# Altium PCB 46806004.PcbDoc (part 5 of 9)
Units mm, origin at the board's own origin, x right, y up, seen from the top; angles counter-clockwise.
Board outline 130 x 105 mm, 8 copper layers (Top Layer, P1-GND, L1-Signal, L2-Signal, L3-Signal, L4-Signal, P2-GND, Bottom Layer), stack 1.63 mm thick; 796 components, 496 nets, 2808 pads, 1195 vias.
Unrouted connection lines stored in the file: 1.
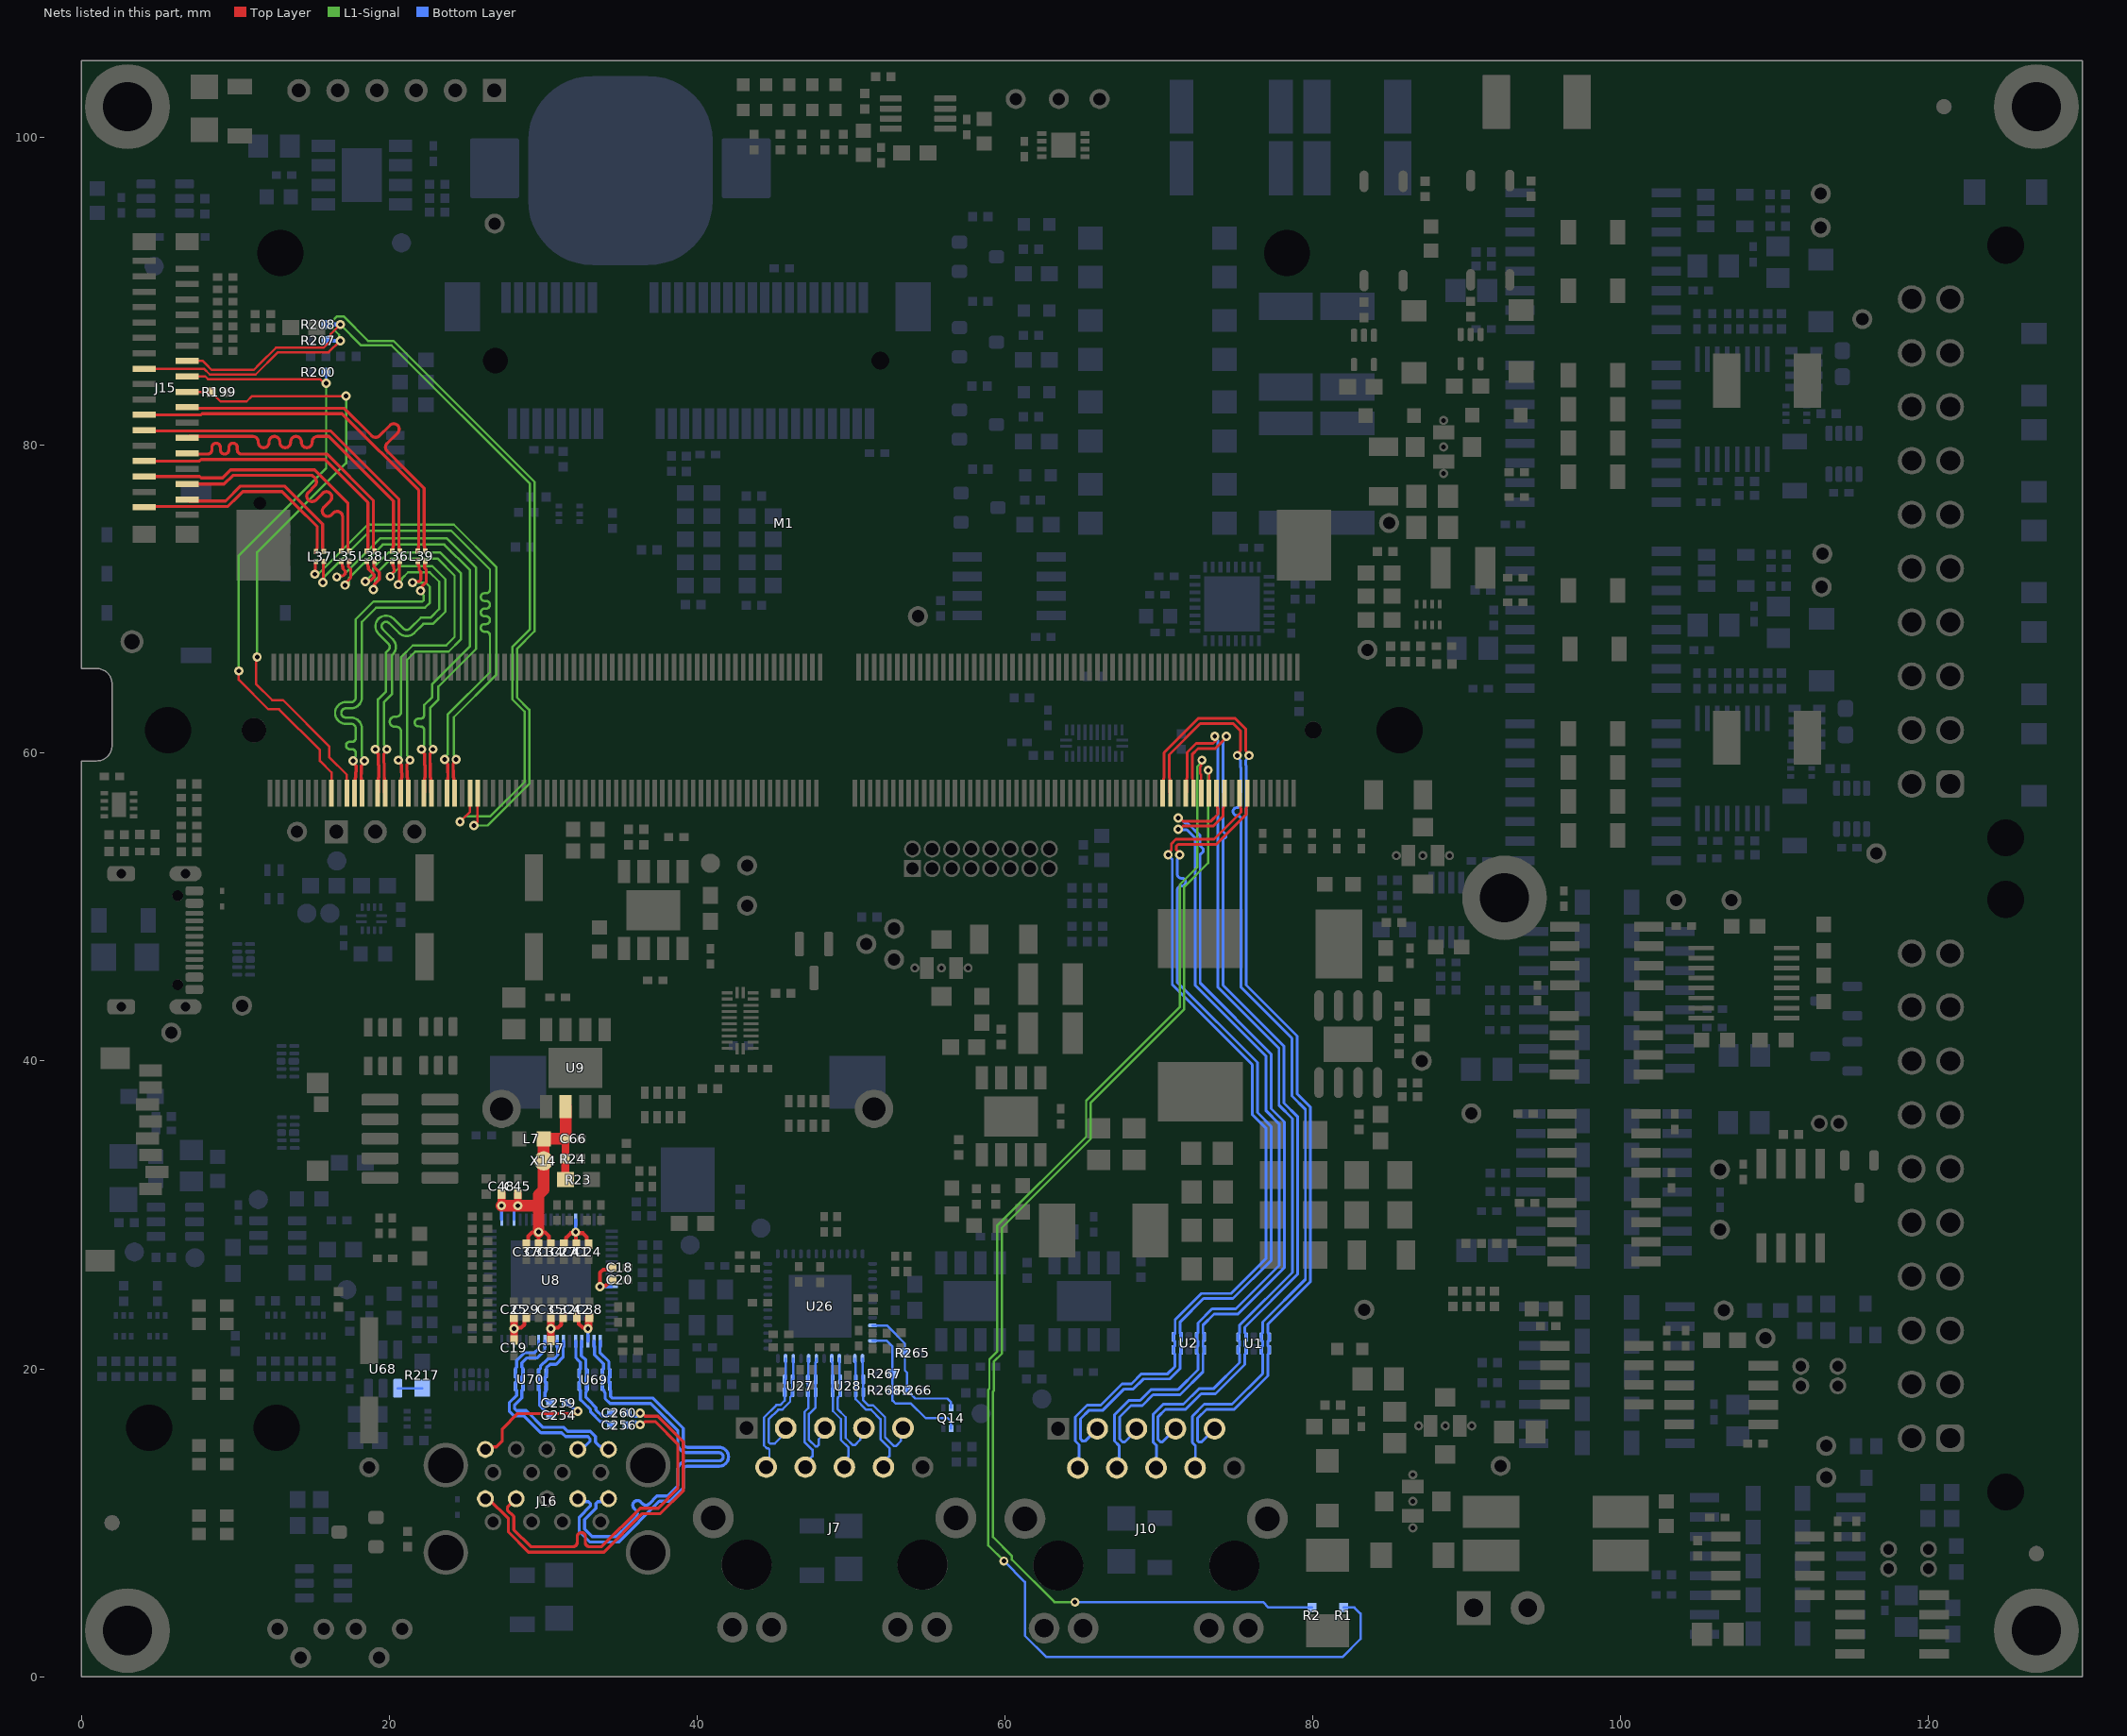
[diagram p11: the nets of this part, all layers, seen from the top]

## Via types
v1: diameter 0.6, hole 0.3, Top Layer to Bottom Layer, tented both sides, 1130 vias
v2: diameter 0.6, hole 0.3, Top Layer to Bottom Layer, 53 vias
v3: diameter 0.3, hole 0.3, Top Layer to Bottom Layer, 12 vias

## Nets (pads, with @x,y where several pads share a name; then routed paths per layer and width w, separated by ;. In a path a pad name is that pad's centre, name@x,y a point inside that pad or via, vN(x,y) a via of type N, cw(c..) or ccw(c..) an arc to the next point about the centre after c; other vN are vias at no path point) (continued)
DS2_P: C259.1 J16.U9 | length 8.5
  Top Layer w0.2: J16.U9@26.25,14.769 26.422,14.941 26.958,14.941 27.35,15.333 27.35,15.644 27.35,16.1 28.35,17.1 30.175,17.1 30.186,17.088 31.982,17.088 32.143,17.249 v1(32.251,17.249)
  Bottom Layer w0.2: C259.1@31.5,17.8 31.55,17.8 31.85,17.5 31.904,17.5 32.154,17.249 v1(32.251,17.249)
DS2_RX_N: J16.U5 U8.44 U70.4 U70.7 | length 13.2
  Bottom Layer w0.2: U8.44@30.111,21.8 30.109,21.798 30.109,21.224 29.592,20.707 28.935,20.707 28.625,20.396 28.625,20.117 28.675,20.067 28.675,19.742 U70.7@28.7,19.717 28.7,19.529 28.675,19.504 28.634,19.504 28.625,19.496 28.625,19.146 28.7,19.071 U70.4@28.7,18.883 28.7,18.695 28.625,18.62 28.625,18.13 28.15,17.655 28.15,17.407 28.267,17.29 28.91,17.29 30,16.2 31.35,16.2 31.599,15.951 33.058,15.951 33.4,15.609 33.4,15.25 33.69,14.96 33.788,14.96 33.881,14.867 33.881,14.769 J16.U5@34.25,14.769
DS2_RX_P: J16.U6 U8.45 U70.5 U70.6 | length 13
  Bottom Layer w0.2: U8.45@29.711,21.8 29.709,21.798 29.709,21.319 29.447,21.057 28.79,21.057 28.275,20.541 28.275,20.117 28.225,20.067 28.225,19.742 U70.6@28.2,19.717 28.2,19.529 28.225,19.504 28.266,19.504 28.275,19.496 28.275,19.146 28.2,19.071 U70.5@28.2,18.883 28.2,18.695 28.275,18.62 28.275,18.275 27.8,17.8 27.8,17.262 28.122,16.94 28.765,16.94 29.855,15.85 31.205,15.85 31.454,15.601 32.913,15.601 33.05,15.464 33.05,15.298 32.521,14.769 J16.U6@32.25,14.769
DS2_TX_N: C254.2 U8.42 U70.2 U70.9 | length 6
  Bottom Layer w0.2: C254.2@30.5,17 30.4,17.1 30.35,17.1 30.15,17.3 30.096,17.3 29.775,17.621 29.775,18.621 29.7,18.695 U70.2@29.7,18.883 29.7,19.071 29.775,19.145 29.775,19.496 29.766,19.504 29.725,19.504 29.7,19.529 U70.9@29.7,19.717 29.7,19.904 29.825,20.029 29.825,20.174 30.301,20.65 30.7,20.65 30.948,20.898 30.948,21.396 30.913,21.431 30.913,21.798 U8.42@30.911,21.8
DS2_TX_P: C259.2 U8.41 U70.1 U70.10 | length 5
  Bottom Layer w0.2: C259.2@30.5,17.8 30.35,17.95 30.242,17.95 30.125,18.067 30.125,18.483 30.175,18.533 30.175,18.858 U70.1@30.2,18.883 30.2,19.071 30.125,19.146 30.125,19.454 30.2,19.529 U70.10@30.2,19.717 30.225,19.742 30.225,20.08 30.445,20.3 30.845,20.3 31.298,20.753 31.298,21.408 31.309,21.419 31.309,21.798 U8.41@31.311,21.8
DS3_N: C256.1 J16.L8 | length 23.5
  Top Layer w0.2: J16.L8@28.25,11.569 27.681,11 27.681,10.835 28.1,10.416 28.1,9.545 29.195,8.45 30.665,8.45 31.95,8.45 ccw(c31.95,8.715) 32.215,8.715 32.215,9.102 cw(c32.481,9.102) 32.746,9.102 32.746,8.715 ccw(c33.011,8.715) 33.011,8.45 33.641,8.45 33.805,8.45 36.305,10.95 37.472,10.95 38.75,12.228 38.75,15.125 37.3,16.575 36.608,16.575 36.408,16.375 v1(36.3,16.375)
  Bottom Layer w0.2: C256.1@35.45,16.35 35.5,16.35 35.725,16.575 36.005,16.575 36.074,16.506 36.169,16.506 v1(36.3,16.375)
DS3_P: C260.1 J16.L9 | length 24.3
  Top Layer w0.2: J16.L9@26.25,11.569 26.452,11.569 27.75,10.271 27.75,9.4 29.05,8.1 33.95,8.1 36.45,10.6 37.617,10.6 39.1,12.083 39.1,15.27 37.445,16.925 36.608,16.925 36.408,17.125 v1(36.3,17.125) v1@36.272,17.125
  Bottom Layer w0.2: C260.1@35.45,17.15 35.5,17.15 35.725,16.925 36.1,16.925 v1(36.3,17.125)
DS3_RX_N: J16.L5 U8.36 U69.4 U69.7 | length 30.1
  Bottom Layer w0.2: U8.36@33.311,21.8 33.311,21.498 33.336,21.473 33.336,20.919 33.925,20.33 33.925,19.98 33.85,19.904 U69.4@33.85,19.717 33.85,19.529 33.875,19.504 33.916,19.504 33.925,19.496 33.925,19.104 33.916,19.096 33.875,19.096 33.85,19.071 33.85,18.695 33.975,18.57 33.975,18.504 34.032,18.447 34.032,18.072 34.354,17.75 37,17.75 38.75,16 38.75,15.448 38.75,15.173 ccw(c39.365,15.173) 39.365,14.558 41.432,14.558 cw(c41.432,14.293) 41.697,14.293 cw(c41.432,14.293) 41.432,14.028 39.365,14.028 ccw(c39.365,13.413) 38.75,13.413 38.75,12.446 38.75,12.4 38.1,11.75 37.405,11.75 37.391,11.736 36.892,11.237 cw(c36.677,11.451) 36.463,11.237 36.342,11.358 ccw(c36.127,11.144) 35.913,11.358 ccw(c36.127,11.144) 35.913,10.93 36.034,10.808 cw(c35.82,10.594) 36.034,10.379 35.563,9.908 34.755,9.1 33.195,9.1 32.7,9.595 32.7,10.221 33.425,10.946 33.425,11.257 33.546,11.378 34.059,11.378 J16.L5@34.25,11.569
DS3_RX_P: J16.L6 U8.35 U69.5 U69.6 | length 30.2
  Bottom Layer w0.2: J16.L6@32.25,11.569 32.441,11.378 32.954,11.378 33.075,11.257 33.075,11.091 32.35,10.366 32.35,9.45 33.05,8.75 34.9,8.75 37.55,11.4 38.245,11.4 39.1,12.255 39.1,12.446 39.1,13.413 cw(c39.365,13.413) 39.365,13.678 41.432,13.678 ccw(c41.432,14.293) 42.047,14.293 ccw(c41.432,14.293) 41.432,14.908 39.365,14.908 cw(c39.365,15.173) 39.1,15.173 39.1,15.448 39.1,16.145 37.145,18.1 34.499,18.1 34.382,18.217 34.382,18.592 34.375,18.599 34.375,18.858 U69.6@34.35,18.883 34.35,19.071 34.325,19.096 34.284,19.096 34.275,19.104 34.275,19.496 34.284,19.504 34.325,19.504 34.35,19.529 U69.5@34.35,19.717 34.35,19.904 34.275,19.98 34.275,20.475 33.686,21.064 33.686,21.473 33.711,21.498 U8.35@33.711,21.8
DS3_TX_N: C256.2 U8.39 U69.1 U69.10 | length 6.9
  Bottom Layer w0.2: U8.39@32.111,21.8 32.111,21.498 32.136,21.473 32.136,20.714 32.25,20.6 32.425,20.425 32.425,19.979 32.35,19.904 U69.1@32.35,19.717 32.35,19.529 32.375,19.504 32.416,19.504 32.425,19.496 32.425,19.145 32.35,19.071 U69.10@32.35,18.883 32.35,18.695 32.425,18.621 32.425,18.006 32.619,17.811 33.086,17.344 33.086,17.194 33.705,16.575 34.175,16.575 34.4,16.35 C256.2@34.45,16.35
DS3_TX_P: C260.2 U8.38 U69.2 U69.9 | length 6.3
  Bottom Layer w0.2: U8.38@32.511,21.8 32.511,21.498 32.486,21.473 32.486,20.859 32.775,20.57 32.775,19.98 32.85,19.904 U69.2@32.85,19.717 32.85,19.529 32.775,19.454 32.775,19.146 32.85,19.071 U69.9@32.85,18.883 32.825,18.858 32.825,18.533 32.775,18.483 32.775,18.151 32.969,17.956 33.436,17.489 33.436,17.339 33.85,16.925 34.175,16.925 34.4,17.15 C260.2@34.45,17.15
DSI_1_CLK_CON_N: J15.9 L38.3 | length 18.6
  Top Layer w0.2: J15.9@6.881,79.478 6.931,79.428 8.111,79.428 8.211,79.428 ccw(c8.211,79.703) 8.486,79.703 8.486,79.866 cw(c8.761,79.866) 8.761,80.141 cw(c8.761,79.866) 9.036,79.866 9.036,79.703 ccw(c9.311,79.703) 9.311,79.428 ccw(c9.311,79.703) 9.586,79.703 9.586,79.866 cw(c9.861,79.866) 9.861,80.141 cw(c9.861,79.866) 10.136,79.866 10.136,79.703 ccw(c10.411,79.703) 10.411,79.428 10.931,79.428 15.972,79.428 18.975,76.425 18.975,73.345 19,73.32 19,73.175 L38.3@19.05,73.125
DSI_1_CLK_CON_P: J15.8 L38.4 | length 18.9
  Top Layer w0.2: J15.8@4.081,78.978 7.685,78.978 7.785,79.078 15.827,79.078 18.625,76.28 18.625,73.317 18.6,73.292 18.6,73.175 L38.4@18.55,73.125
DSI_1_CLK_N: L38.2 M1.35 | length 27.2
  Top Layer w0.2: v1(18.98,70.63) 19.056,70.706 19.056,70.989 19.365,71.298 19.365,71.753 19,72.118 19,72.425 L38.2@19.05,72.475 ; v1(20.6,59.55) 20.6,59.442 20.8,59.242 20.8,58.729 20.825,58.704 20.825,58.424 20.8,58.399 20.8,57.45 M1.35@20.75,57.4
  L1-Signal w0.15: v1(18.98,70.63) 19.066,70.716 19.066,71.211 19.35,71.495 19.35,71.859 20.141,72.65 23.134,72.65 24.25,71.534 24.25,67.55 23.7,67 21.534,67 20.775,66.241 20.775,63.419 20.775,62.694 cw(c20.45,62.694) 20.45,62.369 20.365,62.369 ccw(c20.365,62.044) 20.04,62.044 ccw(c20.365,62.044) 20.365,61.719 20.45,61.719 cw(c20.45,61.394) 20.775,61.394 20.775,60.444 20.775,59.847 20.6,59.672 v1(20.6,59.55)
DSI_1_CLK_P: L38.1 M1.37 | length 26.9
  Top Layer w0.2: v1(18.449,71.16) 18.526,71.236 18.809,71.236 19.015,71.443 19.015,71.608 18.65,71.973 18.65,72.126 18.6,72.176 18.6,72.425 L38.1@18.55,72.475 ; M1.37@21.25,57.4 21.2,57.45 21.2,58.399 21.175,58.424 21.175,58.849 21.15,58.874 21.15,59.242 21.35,59.442 v1(21.35,59.55)
  L1-Signal w0.15: v1(18.449,71.16) 18.95,71.661 18.95,72.025 19.975,73.05 23.3,73.05 24.65,71.7 24.65,67.384 23.866,66.6 21.7,66.6 21.175,66.075 21.175,59.847 21.35,59.672 v1(21.35,59.55)
DSI_1_D0_CON_N: J15.3 L37.3 | length 12.1
  Top Layer w0.2: J15.3@6.881,76.478 6.981,76.378 9.378,76.378 10.35,77.35 13.2,77.35 15.675,74.875 15.675,73.32 15.7,73.295 15.7,73.15 L37.3@15.75,73.1
DSI_1_D0_CON_P: J15.2 L37.4 | length 14.3
  Top Layer w0.2: J15.2@4.081,75.978 4.131,76.028 7.733,76.028 9.523,76.028 10.153,76.658 10.495,77 13.055,77 13.939,76.116 15.325,74.73 15.325,74.218 15.325,73.32 15.3,73.295 15.3,73.15 L37.4@15.25,73.1
DSI_1_D0_N: L37.2 M1.47 | length 33
  Top Layer w0.2: v1(15.7,71.1) 15.725,71.125 15.725,72.425 L37.2@15.75,72.45 ; v1(23.6,59.6) 23.6,59.492 23.8,59.292 23.8,58.757 23.825,58.732 23.825,58.424 23.8,58.399 23.8,57.45 M1.47@23.75,57.4
  L1-Signal w0.15: v1(15.7,71.1) 15.779,71.179 15.779,71.463 18.766,74.45 24.034,74.45 26.55,71.934 26.55,71.217 26.55,70.642 cw(c26.3,70.642) 26.3,70.392 26.2,70.392 ccw(c26.2,70.142) 26.2,69.892 26.3,69.892 cw(c26.3,69.642) 26.3,69.392 26.2,69.392 ccw(c26.2,69.142) 26.2,68.892 26.3,68.892 cw(c26.3,68.642) 26.3,68.392 26.2,68.392 ccw(c26.2,68.142) 26.2,67.892 26.3,67.892 cw(c26.3,67.642) 26.55,67.642 26.55,66.426 26.55,65.25 23.8,62.5 23.8,59.922 23.6,59.722 v1(23.6,59.6)
DSI_1_D0_P: L37.1 M1.49 | length 31.1
  Top Layer w0.2: v1(15.17,71.63) 15.21,71.67 15.21,72.41 L37.1@15.25,72.45 ; M1.49@24.25,57.4 24.2,57.45 24.2,58.399 24.175,58.424 24.175,58.876 24.15,58.901 24.15,59.292 24.35,59.492 v1(24.35,59.6)
  L1-Signal w0.15: v1(15.17,71.63) 15.256,71.716 15.466,71.716 18.6,74.85 24.2,74.85 26.95,72.1 26.95,65.084 24.2,62.334 24.2,59.872 24.35,59.722 v1(24.35,59.6)
DSI_1_D1_CON_N: J15.6 L35.3 | length 17.5
  Top Layer w0.2: J15.6@4.081,77.978 7.685,77.978 7.785,77.878 9.178,77.878 9.7,78.4 15.15,78.4 17.325,76.225 17.325,73.345 17.35,73.32 17.35,73.175 L35.3@17.4,73.125
DSI_1_D1_CON_P: J15.5 L35.4 | length 17.5
  Top Layer w0.2: J15.5@6.881,77.478 9.273,77.478 9.845,78.05 14.472,78.05 15.005,78.05 15.181,77.874 cw(c14.933,77.627) 15.181,77.379 14.747,76.946 ccw(c14.994,76.698) 14.747,76.451 ccw(c14.994,76.698) 15.242,76.451 15.676,76.884 cw(c15.923,76.637) 16.171,76.884 cw(c15.923,76.637) 16.171,76.389 15.758,75.977 ccw(c16.006,75.73) 15.758,75.482 ccw(c16.006,75.73) 16.253,75.482 16.378,75.606 cw(c16.625,75.359) 16.975,75.359 16.975,74.937 16.975,73.317 16.95,73.292 16.95,73.175 L35.4@16.9,73.125
DSI_1_D1_N: L35.2 M1.41 | length 28.3
  Top Layer w0.2: v1(17.13,70.92) 17.13,71.024 17.502,71.396 17.502,71.974 17.35,72.126 17.35,72.425 L35.2@17.4,72.475 ; v1(22.1,60.25) 22.1,60.142 22.3,59.942 22.3,59.23 22.325,59.205 22.325,58.424 22.3,58.399 22.3,57.45 M1.41@22.25,57.4
  L1-Signal w0.15: v1@17.386,70.986 17.386,71.357 19.579,73.55 23.584,73.55 25.25,71.884 25.25,66.95 22.8,64.5 22.8,63.649 22.275,63.124 22.275,63.066 22.275,62.491 cw(c22.025,62.491) 22.025,62.241 21.906,62.241 ccw(c21.906,61.991) 21.906,61.741 22.025,61.741 cw(c22.025,61.491) 22.275,61.491 22.275,60.742 22.275,60.547 22.1,60.372 v1(22.1,60.25)
DSI_1_D1_P: L35.1 M1.43 | length 28.5
  Top Layer w0.2: v1(16.6,71.45) 16.677,71.527 17.016,71.527 17.152,71.663 17.152,71.829 17,71.981 17,72.126 16.95,72.176 16.95,72.425 L35.1@16.9,72.475 ; M1.43@22.75,57.4 22.7,57.45 22.7,58.399 22.675,58.424 22.675,59.35 22.65,59.375 22.65,59.942 22.85,60.142 v1(22.85,60.25)
  L1-Signal w0.15: v1(16.6,71.45) 16.665,71.515 16.978,71.515 19.413,73.95 23.75,73.95 25.65,72.05 25.65,66.784 23.2,64.334 23.2,63.483 22.675,62.958 22.675,60.547 22.85,60.372 v1(22.85,60.25)
DSI_1_D2_CON_N: J15.12 L36.3 | length 21.8
  Top Layer w0.2: J15.12@4.081,80.978 4.131,80.928 16.217,80.928 20.625,76.52 20.625,73.449 20.65,73.424 20.65,73.175 L36.3@20.7,73.125
DSI_1_D2_CON_P: J15.11 L36.4 | length 21.1
  Top Layer w0.2: J15.11@6.881,80.478 6.981,80.578 7.649,80.578 10.348,80.578 11.148,80.578 cw(c11.148,80.228) 11.498,80.228 11.498,80.194 ccw(c11.848,80.194) 12.198,80.194 12.198,80.228 cw(c12.548,80.228) 12.898,80.228 12.898,80.194 ccw(c13.248,80.194) 13.598,80.194 13.598,80.228 cw(c13.948,80.228) 14.298,80.228 14.298,80.194 ccw(c14.648,80.194) 14.998,80.194 14.998,80.228 cw(c15.348,80.228) 15.348,80.578 15.927,80.578 16.072,80.578 20.275,76.375 20.275,73.449 20.25,73.424 20.25,73.175 L36.4@20.2,73.125
DSI_1_D2_N: L36.2 M1.29 | length 23.8
  Top Layer w0.2: v1(19.1,60.25) 19.1,60.142 19.3,59.942 19.3,59.23 19.325,59.205 19.325,58.424 19.3,58.399 19.3,57.45 M1.29@19.25,57.4 ; v1(20.6,70.95) 20.668,71.018 20.668,72.108 20.65,72.126 20.65,72.425 L36.2@20.7,72.475
  L1-Signal w0.15: v1(19.1,60.25) 19.1,60.372 19.275,60.547 19.275,63.491 19.8,64.016 19.8,66.467 19.8,66.546 19.955,66.701 ccw(c19.749,66.906) 19.955,67.112 19.309,67.758 cw(c19.798,68.246) 19.309,68.735 cw(c19.798,68.246) 20.286,68.735 20.875,68.146 20.932,68.089 ccw(c21.138,68.295) 21.343,68.089 22.054,68.8 22.074,68.8 22.684,68.8 23.25,69.366 23.25,71.134 22.634,71.75 21.229,71.75 20.836,71.357 20.836,71.307 20.6,71.072 v1(20.6,70.95)
DSI_1_D2_P: L36.1 M1.31 | length 24.4
  Top Layer w0.2: M1.31@19.75,57.4 19.7,57.45 19.7,58.399 19.675,58.424 19.675,59.35 19.65,59.375 19.65,59.942 19.85,60.142 v1(19.85,60.25) ; v1(20.07,71.48) 20.07,71.55 20.318,71.797 20.318,71.963 20.3,71.981 20.3,72.126 20.25,72.176 20.25,72.425 L36.1@20.2,72.475
  L1-Signal w0.15: v1(19.85,60.25) 19.85,60.372 19.675,60.547 19.675,63.325 20.2,63.85 20.2,66.067 20.2,66.38 20.238,66.418 ccw(c19.749,66.906) 20.238,67.395 19.592,68.041 cw(c19.798,68.246) 19.592,68.452 cw(c19.798,68.246) 20.003,68.452 20.648,67.807 ccw(c21.138,68.295) 21.626,67.806 22.22,68.4 22.474,68.4 22.85,68.4 23.65,69.2 23.65,71.3 22.8,72.15 20.739,72.15 v1(20.07,71.48)
DSI_1_D3_CON_N: J15.15 L39.3 | length 24.4
  Top Layer w0.2: J15.15@6.881,82.478 6.956,82.403 17.092,82.403 18.804,80.691 18.875,80.62 ccw(c19.122,80.868) 19.37,80.62 20.053,81.304 cw(c20.301,81.056) 20.548,81.304 cw(c20.301,81.056) 20.548,80.809 19.865,80.125 ccw(c20.112,79.878) 19.865,79.63 20.4,79.095 20.47,79.025 22.275,77.22 22.275,73.449 22.3,73.424 22.3,73.175 L39.3@22.35,73.125
DSI_1_D3_CON_P: J15.14 L39.4 | length 23.9
  Top Layer w0.2: J15.14@4.081,81.978 7.772,81.978 7.847,82.053 16.947,82.053 21.925,77.075 21.925,73.449 21.9,73.424 21.9,73.175 L39.4@21.85,73.125
DSI_1_D3_N: L39.2 M1.23 | length 21.9
  Top Layer w0.2: v1(17.65,59.5) 17.65,59.392 17.85,59.192 17.85,58.795 17.825,58.77 17.825,58.424 17.8,58.399 17.8,57.45 M1.23@17.75,57.4 ; v1(22.05,70.55) 22.127,70.627 22.127,70.842 22.413,71.129 22.413,71.922 22.3,72.036 22.3,72.425 L39.2@22.35,72.475
  L1-Signal w0.15: v1(17.65,59.5) 17.65,59.622 17.825,59.797 17.825,59.945 17.825,60.02 ccw(c17.585,60.02) 17.585,60.26 17.439,60.26 cw(c17.439,60.5) 17.199,60.5 cw(c17.439,60.5) 17.439,60.74 17.585,60.74 ccw(c17.585,60.98) 17.825,60.98 17.825,61.33 17.825,61.605 ccw(c17.521,61.605) 17.521,61.908 17.192,61.908 cw(c17.192,62.612) 17.192,63.315 17.521,63.315 ccw(c17.521,63.619) 17.825,63.619 17.825,64.415 17.825,68.691 18.984,69.85 22.162,69.85 22.25,69.938 22.25,70.237 22.05,70.437 v1(22.05,70.55)
DSI_1_D3_P: L39.1 M1.25 | length 22.3
  Top Layer w0.2: M1.25@18.25,57.4 18.2,57.45 18.2,58.399 18.175,58.424 18.175,58.625 18.2,58.65 18.2,59.192 18.4,59.392 v1(18.4,59.5) ; v1(21.52,71.08) 21.596,71.157 21.603,71.15 21.939,71.15 22.063,71.274 22.063,71.778 21.95,71.891 21.95,72.126 21.9,72.176 21.9,72.425 L39.1@21.85,72.475
  L1-Signal w0.15: v1(18.4,59.5) 18.4,59.622 18.225,59.797 18.225,61.33 18.225,61.605 ccw(c17.521,61.605) 17.521,62.308 17.192,62.308 cw(c17.192,62.612) 17.192,62.915 17.521,62.915 ccw(c17.521,63.619) 18.225,63.619 18.225,64.415 18.225,68.525 19.15,69.45 22.328,69.45 22.65,69.772 22.65,70.8 22.366,71.084 v1@21.524,71.084
DSI_BKL_EN: J15.17 M1.21 R199.2 | length 41.7
  Top Layer w0.15: J15.17@6.981,83.478 8.422,83.478 R199.2@8.45,83.45 9.05,82.85 10.744,82.85 11.094,83.2 v1(17.2,83.2) ; v1(11.423,66.253) 11.35,66.18 11.35,64.5 12.4,63.45 13.1,63.45 16.1,60.45 16.1,59.748 17.25,58.598 M1.21@17.25,57.4
  L1-Signal w0.15: v1(11.423,66.253) 11.423,73.063 17.2,78.84 v1(17.2,83.2)
DSI_INT: J15.19 M1.17 R200.1 | length 41.7
  Top Layer w0.15: J15.19@6.981,84.478 8.049,84.478 8.227,84.3 15.511,84.3 15.786,84.025 v1(15.908,84.025) ; v1(10.233,65.34) 10.233,64.768 12.151,62.85 12.851,62.85 15.5,60.201 15.5,59.499 16.25,58.749 M1.17@16.25,57.4
  L1-Signal w0.15: v1(10.233,65.34) 10.233,72.833 15.908,78.508 v1(15.908,84.025)
  Bottom Layer w0.15: R200.1@15.9,84.75 15.908,84.742 v1(15.908,84.025)
DSI_SCL: J15.20 M1.55 R207.1 | length 61.3
  Top Layer w0.15: J15.20@4.081,84.978 7.973,84.978 8.351,84.6 11.324,84.6 12.774,86.05 16.072,86.05 v1(16.822,86.8) ; v1(25.5,55.3) 25.75,55.55 M1.55@25.75,57.4
  L1-Signal w0.15: v1(16.822,86.8) 16.754,86.867 16.754,87.175 16.297,87.632 16.297,88.067 16.59,88.36 16.635,88.36 16.65,88.375 17.039,88.375 18.625,86.789 20.278,86.789 29.45,77.617 29.45,67.923 28.3,66.773 28.3,63.624 29.1,62.824 29.1,58 26.4,55.3 v1(25.5,55.3)
  Bottom Layer w0.25: R207.1@15.9,86.8 v1(16.822,86.8)
DSI_SDA: J15.21 M1.53 R208.1 | length 56.7
  Top Layer w0.15: J15.21@6.981,85.478 7.898,85.478 8.098,85.278 8.476,84.9 11.2,84.9 11.578,85.278 12.65,86.35 15.75,86.35 16.2,86.8 16.2,87.228 v1(16.822,87.85) ; v1(24.6,55.55) 25.25,56.2 M1.53@25.25,57.4
  L1-Signal w0.15: v1(16.822,87.85) 18.183,86.489 20.154,86.489 29.15,77.492 29.15,68.047 28,66.897 28,63.5 28.8,62.7 28.8,58.124 26.581,55.905 24.955,55.905 v1(24.6,55.55)
  Bottom Layer w0.25: R208.1@15.9,87.85 v1(16.822,87.85)
DVDD12: C17.2 C18.2 C19.2 C20.1 C24.2 C25.2 C27.1 C29.2 C31.2 C32.2 C34.1 C35.2 C37.2 C38.2 C41.1 C42.2 C45.2 C48.1 C66.2 L7.1 R23.1 R24.2 U8.1 U8.3 U8.7 U8.13 U8.27 U8.37 U8.43 U8.49 U9.6 X14.1 | length 40.2
  Top Layer w0.25: C25.2@28.1,23.35 C25.2@28.106,23.344 ; C19.2@28.106,21.874 C19.2@28.109,21.877 ; v1@28.106,22.6 v1@28.109,22.597 ; v1@28.106,22.612 v1(28.111,22.606) 28.178,22.673 28.573,22.673 28.775,22.875 28.775,23.225 C29.2@28.9,23.35 ; C37.2@28.9,28.1 29.025,28.225 29.025,28.625 29.273,28.873 v1@29.696,28.873 ; C31.2@29.7,28.1 29.706,28.106 v1@29.706,28.883 ; v1@29.739,28.861 30.139,28.861 30.375,28.625 30.375,28.225 C34.1@30.5,28.1 ; C35.2@30.5,23.35 C35.2@30.511,23.339 ; v1(30.511,22.606) 30.578,22.673 30.973,22.673 31.175,22.875 31.175,23.225 C32.2@31.3,23.35 ; C27.1@31.35,28.1 31.475,28.225 31.475,28.515 31.782,28.822 32.044,28.822 v1(32.111,28.889) v1@32.131,28.869 ; R23.1@31.443,32.307 R23.1@31.45,32.3 ; R24.2@31.443,33.65 R24.2@31.465,33.672 ; C41.1@32.15,28.1 32.131,28.119 v1@32.131,28.869 ; C42.2@32.2,23.35 32.325,23.225 32.325,22.925 32.577,22.673 32.844,22.673 v1(32.911,22.606) v1@32.956,22.65 ; C24.2@32.95,28.1 32.825,28.225 32.825,28.562 32.59,28.797 32.59,28.822 32.178,28.822 v1@32.131,28.869 ; C20.1@34.477,25.775 34.427,25.775 34.068,25.417 33.767,25.417 v1(33.7,25.35) 33.7,26.25 33.9,26.45 34.352,26.45 C18.2@34.477,26.575
  Top Layer w0.5: v1(27.3,30.6) C48.1@27.3,31.35 ; v1@28.106,22.612 C25.2@28.106,23.344 ; C19.2@28.109,21.877 v1@28.109,22.597 ; v1(28.35,30.6) C45.2@28.35,31.35 ; C17.2@30.511,21.85 v1(30.511,22.606) C35.2@30.511,23.339 ; R23.1@31.443,32.307 R24.2@31.443,33.65 ; R24.2@31.465,33.672 C66.2@31.465,34.95 ; v1@32.956,22.65 32.956,23.306 C38.2@33,23.35
  Top Layer w0.75: v1(27.3,30.6) v1(28.35,30.6) 29.711,30.6 ; v1(29.711,28.889) 29.711,30.6 ; L7.1@30.033,34.95 X14.1@30.033,33.51 30.033,31.633 29.711,31.311 29.711,30.6 ; L7.1@30.033,34.95 C66.2@31.465,34.95 U9.6@31.465,37.05
  Bottom Layer w0.15: v1(27.3,30.6) v1@27.306,30.594 ; U8.1@27.306,29.7 U8.1@27.311,29.695 ; 28.111,30.24 28.35,30.478 v1(28.35,30.6) ; v1(33.7,25.35) v1@33.703,25.347
  Bottom Layer w0.2: U8.1@27.306,29.7 v1@27.306,30.594 ; U8.49@28.111,21.8 v1(28.111,22.606) ; U8.3@28.111,29.695 28.111,30.24 ; v1(29.711,28.889) U8.7@29.711,29.695 ; U8.43@30.511,21.8 v1(30.511,22.606) ; v1(32.111,28.889) U8.13@32.111,29.695 ; U8.37@32.911,21.8 v1(32.911,22.606) ; v1@33.703,25.347 U8.27@34.459,25.347
ETH1_ACT: M1.237 R2.2 | length 79.9
  Top Layer w0.15: v1(73.2,58.9) 73.25,58.85 M1.237@73.25,57.4
  L1-Signal w0.15: v1(64.55,4.85) 63.213,4.85 60.456,7.607 60.456,7.844 59.225,9.075 59.225,18.53 59.29,18.595 59.29,20.49 59.8,21 59.8,29.177 65.575,34.952 65.575,37.302 71.65,43.377 71.65,51.326 73.2,52.876 v1(73.2,58.9)
  Bottom Layer w0.15: v1(64.55,4.85) 76.773,4.85 77.123,4.5 R2.2@79.95,4.5
ETH1_D0_N: J10.8 M1.227 U1.2 U1.9 | length 63
  Top Layer w0.18: M1.227@70.75,57.4 70.69,57.46 70.69,58.367 70.665,58.392 70.665,59.898 72.687,61.92 74.83,61.92 75.3,61.45 75.3,60.723 75.31,60.713 75.31,60.165 75.1,59.955 v1(75.1,59.85)
  Bottom Layer w0.18: J10.8@72.35,13.569 72.373,13.592 72.373,15.011 72.17,15.213 72.17,16.92 72.95,17.7 74.755,17.7 76.748,19.693 76.748,20.454 76.748,20.956 76.663,21.041 U1.2@76.663,21.228 76.663,21.416 76.727,21.48 76.748,21.48 76.748,21.811 76.727,21.811 76.663,21.875 U1.9@76.663,22.062 76.663,22.25 76.748,22.335 76.748,23.048 79.52,25.82 79.52,36.863 78.65,37.733 78.65,41.483 75.335,44.798 75.335,55.608 75.335,55.698 ccw(c75.08,55.698) 75.08,55.954 75.07,55.954 cw(c75.07,56.209) 75.07,56.464 75.08,56.464 ccw(c75.08,56.719) 75.335,56.719 75.335,57.09 75.335,59.062 75.31,59.087 75.31,59.535 75.1,59.745 v1(75.1,59.85)
ETH1_D0_P: J10.9 M1.225 U1.1 U1.10 | length 63.1
  Top Layer w0.18: M1.225@70.25,57.4 70.31,57.46 70.31,58.367 70.335,58.392 70.335,60.035 72.55,62.25 74.967,62.25 75.63,61.587 75.63,60.86 75.64,60.85 75.64,60.165 75.85,59.955 v1(75.85,59.85)
  Bottom Layer w0.18: J10.9@73.62,16.109 72.755,15.244 72.606,15.244 72.5,15.35 72.5,16.783 73.087,17.37 74.892,17.37 77.078,19.556 77.078,20.318 77.078,20.956 77.163,21.041 U1.1@77.163,21.228 77.163,21.416 77.099,21.48 77.078,21.48 77.078,21.811 77.099,21.811 77.163,21.875 U1.10@77.163,22.062 77.163,22.25 77.078,22.335 77.078,22.911 79.85,25.683 79.85,37 78.98,37.87 78.98,41.62 75.665,44.935 75.665,59.199 75.64,59.224 75.64,59.535 75.85,59.745 v1(75.85,59.85)
ETH1_D1_N: J10.6 M1.231 U1.5 U1.6 | length 60.2
  Top Layer w0.18: M1.231@71.75,57.4 71.81,57.46 71.81,58.367 71.835,58.392 71.835,60.052 72.413,60.63 73.53,60.63 73.739,60.839 73.714,60.863 73.714,61.013 v1(73.634,61.093)
  Bottom Layer w0.18: J10.6@69.81,13.569 69.853,13.612 69.853,15.031 69.62,15.263 69.62,17.037 70.283,17.7 71.6,17.7 72.61,18.71 73.545,18.71 75.248,20.412 75.248,20.956 75.163,21.041 U1.5@75.163,21.228 75.163,21.416 75.226,21.48 75.248,21.48 75.248,21.811 75.226,21.811 75.163,21.875 U1.6@75.163,22.062 75.163,22.25 75.248,22.335 75.248,22.848 78.67,26.27 78.67,36.263 77.8,37.133 77.8,40.833 73.844,44.79 73.844,60.777 73.634,60.987 v1(73.634,61.093)
ETH1_D1_P: J10.7 M1.233 U1.4 U1.7 | length 60
  Top Layer w0.18: M1.233@72.25,57.4 72.19,57.46 72.19,58.367 72.165,58.392 72.165,59.915 72.55,60.3 73.667,60.3 74.384,61.017 v1(74.384,61.093)
  Bottom Layer w0.18: J10.7@71.08,16.109 70.235,15.264 70.086,15.264 69.95,15.4 69.95,16.9 70.42,17.37 71.737,17.37 72.747,18.38 73.682,18.38 75.578,20.276 75.578,20.956 75.663,21.041 U1.4@75.663,21.228 75.663,21.416 75.599,21.48 75.578,21.48 75.578,21.811 75.599,21.811 75.663,21.875 U1.7@75.663,22.062 75.663,22.25 75.578,22.335 75.578,22.711 79,26.133 79,36.4 78.13,37.27 78.13,40.97 74.174,44.926 74.174,54.374 74.35,54.55 74.35,54.729 74.174,54.905 74.174,60.777 74.384,60.987 v1(74.384,61.093)
ETH1_D2_N: J10.4 M1.241 U2.2 U2.9 | length 56.5
  Top Layer w0.18: v1(71.25,55.05) 71.355,55.05 71.565,55.26 73.525,55.26 74.165,55.9 74.165,56.408 74.19,56.433 74.19,57.34 M1.241@74.25,57.4
  Bottom Layer w0.18: J10.4@67.27,13.569 67.412,13.711 67.412,15.021 67.12,15.313 67.12,17.02 68.05,17.95 68.783,17.95 69.483,18.65 71.235,18.65 72.535,19.95 72.535,20.658 72.535,20.968 72.45,21.053 U2.2@72.45,21.241 72.45,21.428 72.514,21.492 72.535,21.492 72.535,21.823 72.514,21.823 72.45,21.887 U2.9@72.45,22.075 72.45,22.262 72.535,22.347 72.535,22.985 73.45,23.9 75,23.9 77.82,26.72 77.82,35.913 76.97,36.763 76.97,40.313 72.35,44.933 72.35,54.5 71.82,55.03 71.27,55.03 v1(71.25,55.05)
ETH1_D2_P: J10.5 M1.239 U2.1 U2.10 | length 56.3
  Top Layer w0.18: v1(71.25,55.8) 71.355,55.8 71.565,55.59 73.388,55.59 73.835,56.037 73.835,56.408 73.81,56.433 73.81,57.34 M1.239@73.75,57.4
  Bottom Layer w0.18: J10.5@68.54,16.109 68.54,16 67.795,15.255 67.645,15.255 67.45,15.45 67.45,16.883 68.187,17.62 68.92,17.62 69.62,18.32 71.372,18.32 72.865,19.813 72.865,20.522 72.865,20.968 72.95,21.053 U2.1@72.95,21.241 72.95,21.428 72.886,21.492 72.865,21.492 72.865,21.823 72.886,21.823 72.95,21.887 U2.10@72.95,22.075 72.95,22.262 72.865,22.347 72.865,22.848 73.587,23.57 75.137,23.57 78.15,26.583 78.15,36.05 77.3,36.9 77.3,40.45 72.68,45.07 72.68,53.408 72.893,53.622 72.893,53.771 72.68,53.984 72.68,54.637 71.87,55.446 71.703,55.446 71.349,55.8 v1(71.25,55.8)
ETH1_D3_N: J10.2 M1.245 U2.5 U2.6 | length 58.4
  Top Layer w0.18: v1(70.6,53.4) 70.6,53.505 70.81,53.715 70.81,54.107 71.109,54.405 73.589,54.405 75.335,56.152 75.335,56.408 75.31,56.433 75.31,57.34 M1.245@75.25,57.4
  Bottom Layer w0.18: J10.2@64.73,13.569 64.813,13.652 64.813,15.071 64.57,15.313 64.57,16.887 65.333,17.65 66.233,17.65 67.613,19.03 68.213,19.03 68.863,19.68 70.565,19.68 71.035,20.15 71.035,20.968 70.95,21.053 U2.5@70.95,21.241 70.95,21.428 71.014,21.492 71.035,21.492 71.035,21.823 71.014,21.823 70.95,21.887 U2.6@70.95,22.075 70.95,22.262 70.985,22.297 71.057,22.297 71.057,22.387 ; v1(70.6,53.4) 70.6,53.355 70.87,53.085 70.87,44.963 76.07,39.763 76.07,36.513 76.97,35.613 76.97,27.187 74.683,24.9 72.761,24.9 71.057,23.196 71.057,22.387
ETH1_D3_P: J10.3 M1.247 U2.4 U2.7 | length 58.4
  Top Layer w0.18: v1(71.35,53.4) 71.35,53.505 71.14,53.715 71.14,53.97 71.245,54.075 73.725,54.075 75.665,56.015 75.665,56.408 75.69,56.433 75.69,57.34 M1.247@75.75,57.4
  Bottom Layer w0.18: J10.3@66,16.109 65.195,15.304 65.046,15.304 64.9,15.45 64.9,16.75 65.47,17.32 66.37,17.32 67.75,18.7 68.35,18.7 69,19.35 70.702,19.35 71.365,20.013 71.365,20.968 71.45,21.053 U2.4@71.45,21.241 71.45,21.428 71.386,21.492 71.365,21.492 71.365,21.823 71.386,21.823 71.45,21.887 U2.7@71.45,22.075 71.45,22.262 71.415,22.297 U2.7@71.388,22.297 ; v1(71.35,53.4) 71.35,53.286 71.2,53.136 71.2,52.657 71.2,52.133 ccw(c71.455,52.133) 71.455,51.878 71.48,51.878 cw(c71.48,51.623) 71.48,51.368 71.455,51.368 ccw(c71.455,51.113) 71.2,51.113 71.2,50.513 71.2,45.1 76.4,39.9 76.4,36.65 77.3,35.75 77.3,27.05 74.82,24.57 72.898,24.57 71.387,23.06 U2.7@71.387,22.298
ETH1_LINK: M1.235 R1.2 | length 91.6
  Top Layer w0.15: M1.235@72.75,57.4 72.75,58.608 72.675,58.683 72.675,59.117 72.733,59.175 72.733,59.483 v1(72.8,59.55)
  L1-Signal w0.15: v1(59.931,7.519) 58.925,8.525 58.925,18.654 58.99,18.719 58.99,20.614 59.49,21.114 59.49,29.291 65.275,35.076 65.275,37.426 71.35,43.501 71.35,51.45 72.5,52.6 72.5,59.128 72.8,59.428 v1(72.8,59.55)
  Bottom Layer w0.15: v1(59.931,7.519) 61.3,6.15 61.3,2.672 62.672,1.3 81.95,1.3 83.1,2.45 83.1,4.1 82.7,4.5 R1.2@82,4.5
ETH2_ACT: Q14.5 R267.2 R268.1 U26.47 | length 9.8
  Bottom Layer w0.15: U26.47@51.4,21.825 52.325,21.825 52.7,21.45 R267.2@52.7,19.672 R268.1@52.7,18.6 52.7,17.95 52.9,17.75 53.9,17.75 54.85,16.8 56.284,16.8 56.5,16.584 Q14.5@56.5,16.125
ETH2_D0_N: J7.8 U26.2 U28.4 U28.7 | length 8.3
  Bottom Layer w0.15: U26.2@50.25,20.675 50.25,20.471 50.3,20.421 U28.4@50.3,19.317 U28.7@50.3,18.483 50.3,18.038 50.994,17.343 51.307,17.343 51.912,16.738 51.912,15.438 52.5,14.85 52.5,14.332 52.11,13.942 J7.8@52.11,13.619
ETH2_D0_P: J7.9 U26.1 U28.5 U28.6 | length 8.2
  Bottom Layer w0.15: U26.1@50.75,20.675 50.75,19.367 U28.5@50.8,19.317 U28.6@50.8,18.483 50.8,17.962 51.119,17.643 51.431,17.643 52.212,16.862 52.212,15.562 52.786,14.989 52.91,14.989 53.243,15.322 53.243,16.022 J7.9@53.38,16.159
ETH2_D1_N: J7.6 U26.5 U28.1 U28.10 | length 7.6
  Bottom Layer w0.15: U26.5@48.75,20.675 48.75,20.471 48.8,20.421 U28.1@48.8,19.317 U28.10@48.8,18.483 48.825,18.458 48.825,17.266 49.35,16.741 49.35,15.388 49.844,14.894 49.844,14.332 49.809,14.297 49.809,13.858 J7.6@49.57,13.619
ETH2_D1_P: J7.7 U26.4 U28.2 U28.9 | length 7.6
  Bottom Layer w0.15: U26.4@49.25,20.675 49.25,19.367 U28.2@49.3,19.317 U28.9@49.3,18.483 49.3,18.296 49.25,18.246 49.238,18.246 49.15,18.158 49.15,18.114 49.125,18.089 49.125,17.391 49.65,16.866 49.65,15.512 50.119,15.043 50.243,15.043 50.601,15.401 50.601,15.92 J7.7@50.84,16.159
ETH2_D2_N: J7.4 U26.8 U27.4 U27.7 | length 7.6
  Bottom Layer w0.15: J7.4@47.03,13.619 47.03,13.868 47.494,14.332 47.494,14.744 46.975,15.263 46.975,17.199 47.225,17.449 47.225,18.458 U27.7@47.2,18.483 U27.4@47.2,19.317 47.233,19.35 47.233,20.658 U26.8@47.25,20.675
ETH2_D2_P: J7.5 U26.7 U27.5 U27.6 | length 7.6
  Bottom Layer w0.15: U26.7@47.75,20.675 47.75,20.471 47.7,20.421 U27.6@47.7,18.483 47.7,17.5 47.275,17.075 47.275,15.387 47.688,14.974 47.812,14.974 47.9,15.062 47.9,15.421 48.3,15.821 J7.5@48.3,16.159
ETH2_D3_N: J7.2 U26.11 U27.1 U27.10 | length 8.1
  Bottom Layer w0.15: J7.2@44.49,13.619 44.7,13.829 44.7,14.762 44.612,14.85 44.526,14.85 44.35,15.026 44.35,16.85 45.15,17.65 45.4,17.65 45.7,17.95 U27.10@45.7,18.483 U27.1@45.7,19.317 45.75,19.367 U26.11@45.75,20.675
ETH2_D3_P: J7.3 U26.10 U27.2 U27.9 | length 7.9
  Bottom Layer w0.15: J7.3@45.76,16.159 45.76,15.86 45.05,15.15 44.738,15.15 44.65,15.238 44.65,16.726 45.274,17.35 45.524,17.35 45.681,17.507 46.05,17.876 46.05,18.158 46.138,18.246 46.15,18.246 46.2,18.296 U27.9@46.2,18.389 ; U27.9@46.2,18.483 U27.2@46.2,19.317 46.25,19.367 U26.10@46.25,20.675
ETH2_LINK: Q14.2 R265.2 R266.1 U26.45 | length 9.2
  Bottom Layer w0.15: U26.45@51.4,22.825 52.325,22.825 53.5,21.65 53.5,19.9 53.65,19.75 R266.1@53.65,18.6 54.175,18.075 56.266,18.075 56.5,17.841 Q14.2@56.5,17.475
FAULTn: R217.1 U68.4 | length 1.6
  Bottom Layer w0.15: U68.4@20.561,18.745 22.145,18.745 R217.1@22.15,18.75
